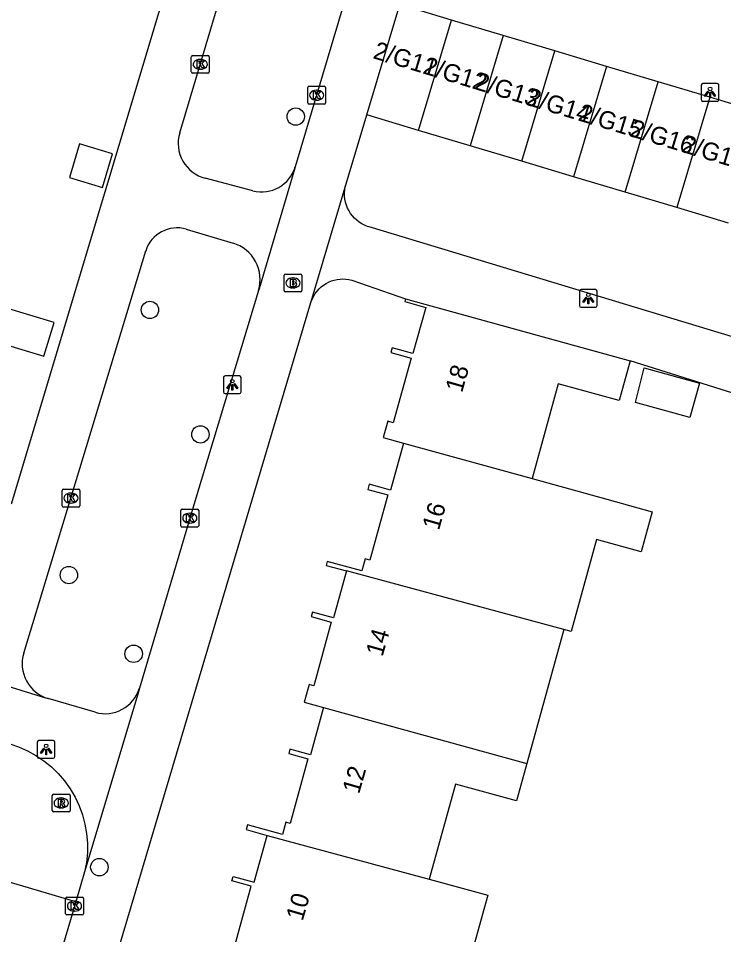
# Model space of a CAD drawing. Extents: x 162186 to 163152, y 385513 to 386513.
# Drawn here: x 162732.3 to 162772, y 386113.9 to 386165.5 of the extents above; entities that cross this region are included whole.
import ezdxf

# ---------------------------------------------------------------- set-up
doc = ezdxf.new("R2010")
doc.units = 0
for name, color, linetype in [('IMGEO_Boom', 7, 'Continuous'), ('IMGEO_Brandkraan', 7, 'Continuous'), ('IMGEO_Kolk', 7, 'Continuous'), ('IMGEO_Lichtpunt', 7, 'Continuous'), ('IMGEO_Pand', 7, 'Continuous'), ('IMGEO_Pand_nummerreeks', 7, 'Continuous'), ('IMGEO_Rijbaan_lokaal_open', 7, 'Continuous'), ('IMGEO_Rioolput', 7, 'Continuous'), ('IMGEO_Voetpad_open', 7, 'Continuous')]:
    doc.layers.add(name, color=color, linetype=linetype)

msp = doc.modelspace()

# ---------------------------------------------------------------- linework, layer by layer
at = {"layer": 'IMGEO_Boom'}
for centre in [(162747.869, 386159.924), (162739.661, 386149.049), (162742.506, 386142.04), (162735.099, 386134.127), (162738.747, 386129.698), (162736.815, 386117.693)]:
    msp.add_circle(centre, 0.489, dxfattribs=at)
at = {"layer": 'IMGEO_Brandkraan'}
for p, q in [((162747.21, 386150.141), (162747.21, 386150.993)), ((162747.285, 386151.067), (162748.137, 386151.067)), ((162748.211, 386150.993), (162748.211, 386150.141)), ((162747.698, 386150.847), (162747.723, 386150.847)), ((162748.137, 386150.067), (162747.285, 386150.067)), ((162747.721, 386150.287), (162747.696, 386150.287))]:
    msp.add_line(p, q, dxfattribs=at)
for points in [[(162747.21, 386150.141), (162747.21, 386150.993)], [(162747.285, 386151.067), (162748.137, 386151.067)], [(162748.211, 386150.993), (162748.211, 386150.141)], [(162747.558, 386150.767), (162747.558, 386150.367), (162747.771, 386150.367)], [(162747.789, 386150.767), (162747.558, 386150.767)], [(162747.737, 386150.686), (162747.683, 386150.686), (162747.683, 386150.61)], [(162747.683, 386150.61), (162747.736, 386150.61)], [(162747.745, 386150.534), (162747.683, 386150.534), (162747.683, 386150.453)], [(162747.683, 386150.453), (162747.745, 386150.453)], [(162748.137, 386150.067), (162747.285, 386150.067)]]:
    msp.add_lwpolyline(points, dxfattribs=at)
for centre, radius, start, end in [((162747.287, 386150.991), 0.0765, 91.552, 178.448), ((162747.287, 386150.991), 0.0765, 91.552, 178.448), ((162748.135, 386150.991), 0.0765, 1.552, 88.448), ((162748.135, 386150.991), 0.0765, 1.552, 88.448), ((162747.738, 386150.648), 0.0379, 267.8285, 90.9355), ((162747.746, 386150.493), 0.0404, 269.8759, 90.5077), ((162747.793, 386150.622), 0.145, 59.4692, 91.5367), ((162747.818, 386150.669), 0.0922, 285.5137, 58.1501), ((162747.823, 386150.477), 0.105, 301.3115, 78.989), ((162747.287, 386150.143), 0.0765, 181.552, 268.448), ((162747.287, 386150.143), 0.0765, 181.552, 268.448), ((162747.777, 386150.618), 0.251, 268.6676, 293.5347), ((162748.135, 386150.143), 0.0765, 271.552, 358.448), ((162748.135, 386150.143), 0.0765, 271.552, 358.448)]:
    msp.add_arc(centre, radius, start, end, dxfattribs=at)
for centre, major_axis, ratio, start_param, end_param in [((162747.697, 386150.567), (-0.387, 0.002), 0.722429, 4.712389, 7.853982), ((162747.722, 386150.567), (-0.39, 0.002), 0.717154, 1.570796, 4.712389)]:
    msp.add_ellipse(centre, major_axis=major_axis, ratio=ratio, start_param=start_param, end_param=end_param, dxfattribs=at)
at = {"layer": 'IMGEO_Kolk'}
for p, q in [((162742.068, 386163.365), (162742.92, 386163.365)), ((162741.993, 386162.439), (162741.993, 386163.291)), ((162742.481, 386163.145), (162742.506, 386163.145)), ((162742.994, 386163.291), (162742.994, 386162.439)), ((162742.92, 386162.365), (162742.068, 386162.365)), ((162742.504, 386162.585), (162742.479, 386162.585)), ((162748.544, 386160.702), (162748.544, 386161.554)), ((162748.619, 386161.628), (162749.471, 386161.628)), ((162749.032, 386161.408), (162749.057, 386161.408)), ((162749.545, 386161.554), (162749.545, 386160.702)), ((162749.055, 386160.848), (162749.03, 386160.848)), ((162749.471, 386160.628), (162748.619, 386160.628)), ((162734.718, 386138.031), (162734.718, 386138.883)), ((162734.793, 386138.957), (162735.645, 386138.957)), ((162735.206, 386138.737), (162735.231, 386138.737)), ((162735.719, 386138.883), (162735.719, 386138.031)), ((162735.229, 386138.177), (162735.204, 386138.177)), ((162735.645, 386137.957), (162734.793, 386137.957)), ((162741.407, 386136.905), (162741.407, 386137.757)), ((162741.482, 386137.831), (162742.334, 386137.831)), ((162741.895, 386137.611), (162741.92, 386137.611)), ((162742.408, 386137.757), (162742.408, 386136.905)), ((162741.918, 386137.051), (162741.893, 386137.051)), ((162742.334, 386136.831), (162741.482, 386136.831)), ((162734.917, 386115.077), (162734.917, 386115.929)), ((162734.992, 386116.003), (162735.844, 386116.003)), ((162735.918, 386115.929), (162735.918, 386115.077)), ((162735.405, 386115.783), (162735.43, 386115.783)), ((162735.844, 386115.003), (162734.992, 386115.003)), ((162735.428, 386115.223), (162735.403, 386115.223))]:
    msp.add_line(p, q, dxfattribs=at)
for points in [[(162742.068, 386163.365), (162742.92, 386163.365)], [(162741.993, 386162.439), (162741.993, 386163.291)], [(162742.314, 386163.065), (162742.437, 386163.065), (162742.437, 386162.914), (162742.567, 386163.065), (162742.731, 386163.065), (162742.585, 386162.914), (162742.738, 386162.665), (162742.586, 386162.665), (162742.501, 386162.829), (162742.437, 386162.762), (162742.437, 386162.665), (162742.314, 386162.665), (162742.314, 386163.065)], [(162742.994, 386163.291), (162742.994, 386162.439)], [(162742.92, 386162.365), (162742.068, 386162.365)], [(162748.544, 386160.702), (162748.544, 386161.554)], [(162748.619, 386161.628), (162749.471, 386161.628)], [(162748.865, 386161.328), (162748.988, 386161.328), (162748.988, 386161.177), (162749.118, 386161.328), (162749.282, 386161.328), (162749.136, 386161.177), (162749.289, 386160.928), (162749.137, 386160.928), (162749.052, 386161.092), (162748.988, 386161.025), (162748.988, 386160.928), (162748.865, 386160.928), (162748.865, 386161.328)], [(162749.545, 386161.554), (162749.545, 386160.702)], [(162749.471, 386160.628), (162748.619, 386160.628)], [(162734.718, 386138.031), (162734.718, 386138.883)], [(162734.793, 386138.957), (162735.645, 386138.957)], [(162735.039, 386138.657), (162735.162, 386138.657), (162735.162, 386138.506), (162735.292, 386138.657), (162735.456, 386138.657), (162735.31, 386138.506), (162735.463, 386138.257), (162735.311, 386138.257), (162735.226, 386138.421), (162735.162, 386138.354), (162735.162, 386138.257), (162735.039, 386138.257), (162735.039, 386138.657)], [(162735.719, 386138.883), (162735.719, 386138.031)], [(162735.645, 386137.957), (162734.793, 386137.957)], [(162741.407, 386136.905), (162741.407, 386137.757)], [(162741.482, 386137.831), (162742.334, 386137.831)], [(162742.408, 386137.757), (162742.408, 386136.905)], [(162741.728, 386137.531), (162741.851, 386137.531), (162741.851, 386137.38), (162741.981, 386137.531), (162742.145, 386137.531), (162741.999, 386137.38), (162742.152, 386137.131), (162742, 386137.131), (162741.915, 386137.295), (162741.851, 386137.228), (162741.851, 386137.131), (162741.728, 386137.131), (162741.728, 386137.531)], [(162742.334, 386136.831), (162741.482, 386136.831)], [(162734.917, 386115.077), (162734.917, 386115.929)], [(162734.992, 386116.003), (162735.844, 386116.003)], [(162735.918, 386115.929), (162735.918, 386115.077)], [(162735.238, 386115.703), (162735.361, 386115.703), (162735.361, 386115.552), (162735.491, 386115.703), (162735.655, 386115.703), (162735.509, 386115.552), (162735.662, 386115.303), (162735.51, 386115.303), (162735.425, 386115.467), (162735.361, 386115.4), (162735.361, 386115.303), (162735.238, 386115.303), (162735.238, 386115.703)], [(162735.844, 386115.003), (162734.992, 386115.003)]]:
    msp.add_lwpolyline(points, dxfattribs=at)
for centre, start, end in [((162742.07, 386163.289), 91.552, 178.448), ((162742.07, 386163.289), 91.552, 178.448), ((162742.918, 386163.289), 1.552, 88.448), ((162742.918, 386163.289), 1.552, 88.448), ((162742.07, 386162.441), 181.552, 268.448), ((162742.07, 386162.441), 181.552, 268.448), ((162742.918, 386162.441), 271.552, 358.448), ((162742.918, 386162.441), 271.552, 358.448), ((162748.621, 386161.552), 91.552, 178.448), ((162748.621, 386161.552), 91.552, 178.448), ((162749.469, 386161.552), 1.552, 88.448), ((162749.469, 386161.552), 1.552, 88.448), ((162748.621, 386160.704), 181.552, 268.448), ((162748.621, 386160.704), 181.552, 268.448), ((162749.469, 386160.704), 271.552, 358.448), ((162749.469, 386160.704), 271.552, 358.448), ((162734.795, 386138.881), 91.552, 178.448), ((162734.795, 386138.881), 91.552, 178.448), ((162735.643, 386138.881), 1.552, 88.448), ((162735.643, 386138.881), 1.552, 88.448), ((162734.795, 386138.033), 181.552, 268.448), ((162734.795, 386138.033), 181.552, 268.448), ((162735.643, 386138.033), 271.552, 358.448), ((162735.643, 386138.033), 271.552, 358.448), ((162741.484, 386137.755), 91.552, 178.448), ((162741.484, 386137.755), 91.552, 178.448), ((162742.332, 386137.755), 1.552, 88.448), ((162742.332, 386137.755), 1.552, 88.448), ((162741.484, 386136.907), 181.552, 268.448), ((162741.484, 386136.907), 181.552, 268.448), ((162742.332, 386136.907), 271.552, 358.448), ((162742.332, 386136.907), 271.552, 358.448), ((162734.994, 386115.927), 91.552, 178.448), ((162734.994, 386115.927), 91.552, 178.448), ((162735.842, 386115.927), 1.552, 88.448), ((162735.842, 386115.927), 1.552, 88.448), ((162734.994, 386115.079), 181.552, 268.448), ((162734.994, 386115.079), 181.552, 268.448), ((162735.842, 386115.079), 271.552, 358.448), ((162735.842, 386115.079), 271.552, 358.448)]:
    msp.add_arc(centre, 0.0765, start, end, dxfattribs=at)
for centre, major_axis, ratio, start_param, end_param in [((162742.48, 386162.865), (-0.387, 0.002), 0.722429, 4.712389, 7.853982), ((162742.505, 386162.865), (-0.39, 0.002), 0.717154, 1.570796, 4.712389), ((162749.031, 386161.128), (-0.387, 0.002), 0.722429, 4.712389, 7.853982), ((162749.056, 386161.128), (-0.39, 0.002), 0.717154, 1.570796, 4.712389), ((162735.205, 386138.457), (-0.387, 0.002), 0.722429, 4.712389, 7.853982), ((162735.23, 386138.457), (-0.39, 0.002), 0.717154, 1.570796, 4.712389), ((162741.894, 386137.331), (-0.387, 0.002), 0.722429, 4.712389, 7.853982), ((162741.919, 386137.331), (-0.39, 0.002), 0.717154, 1.570796, 4.712389), ((162735.404, 386115.503), (-0.387, 0.002), 0.722429, 4.712389, 7.853982), ((162735.429, 386115.503), (-0.39, 0.002), 0.717154, 1.570796, 4.712389)]:
    msp.add_ellipse(centre, major_axis=major_axis, ratio=ratio, start_param=start_param, end_param=end_param, dxfattribs=at)
at = {"layer": 'IMGEO_Lichtpunt'}
for p, q in [((162770.694, 386161.684), (162770.694, 386160.877)), ((162770.694, 386161.684), (162770.694, 386160.877)), ((162771.596, 386161.779), (162770.788, 386161.779)), ((162771.596, 386161.779), (162770.788, 386161.779)), ((162771.69, 386160.877), (162771.69, 386161.684)), ((162771.69, 386160.877), (162771.69, 386161.684)), ((162770.788, 386160.783), (162771.596, 386160.783)), ((162770.788, 386160.783), (162771.596, 386160.783)), ((162763.837, 386150.097), (162763.837, 386149.29)), ((162763.837, 386150.097), (162763.837, 386149.29)), ((162764.739, 386150.192), (162763.931, 386150.192)), ((162764.739, 386150.192), (162763.931, 386150.192)), ((162764.833, 386149.29), (162764.833, 386150.097)), ((162764.833, 386149.29), (162764.833, 386150.097)), ((162763.931, 386149.196), (162764.739, 386149.196)), ((162763.931, 386149.196), (162764.739, 386149.196)), ((162744.701, 386145.333), (162743.893, 386145.333)), ((162744.701, 386145.333), (162743.893, 386145.333)), ((162743.799, 386145.238), (162743.799, 386144.431)), ((162743.799, 386145.238), (162743.799, 386144.431)), ((162744.795, 386144.431), (162744.795, 386145.238)), ((162744.795, 386144.431), (162744.795, 386145.238)), ((162743.893, 386144.337), (162744.701, 386144.337)), ((162743.893, 386144.337), (162744.701, 386144.337)), ((162733.321, 386124.724), (162733.321, 386123.917)), ((162733.321, 386124.724), (162733.321, 386123.917)), ((162734.223, 386124.819), (162733.415, 386124.819)), ((162734.223, 386124.819), (162733.415, 386124.819)), ((162734.317, 386123.917), (162734.317, 386124.724)), ((162734.317, 386123.917), (162734.317, 386124.724)), ((162733.415, 386123.823), (162734.223, 386123.823)), ((162733.415, 386123.823), (162734.223, 386123.823))]:
    msp.add_line(p, q, dxfattribs=at)
for points in [[(162771.068, 386161.348), (162771.107, 386161.32), (162770.919, 386161.058), (162770.881, 386161.085), (162771.068, 386161.348)], [(162771.17, 386161.3), (162771.217, 386161.3), (162771.217, 386160.978), (162771.17, 386160.978), (162771.17, 386161.3)], [(162771.28, 386161.32), (162771.318, 386161.347), (162771.505, 386161.085), (162771.466, 386161.057), (162771.28, 386161.32)], [(162764.211, 386149.761), (162764.25, 386149.733), (162764.062, 386149.471), (162764.024, 386149.498), (162764.211, 386149.761)], [(162764.313, 386149.713), (162764.36, 386149.713), (162764.36, 386149.391), (162764.313, 386149.391), (162764.313, 386149.713)], [(162764.423, 386149.733), (162764.461, 386149.76), (162764.648, 386149.498), (162764.609, 386149.47), (162764.423, 386149.733)], [(162744.173, 386144.902), (162744.212, 386144.874), (162744.024, 386144.612), (162743.986, 386144.639), (162744.173, 386144.902)], [(162744.275, 386144.854), (162744.322, 386144.854), (162744.322, 386144.532), (162744.275, 386144.532), (162744.275, 386144.854)], [(162744.385, 386144.874), (162744.423, 386144.901), (162744.61, 386144.639), (162744.571, 386144.611), (162744.385, 386144.874)], [(162733.695, 386124.388), (162733.734, 386124.36), (162733.546, 386124.098), (162733.508, 386124.125), (162733.695, 386124.388)], [(162733.797, 386124.34), (162733.844, 386124.34), (162733.844, 386124.018), (162733.797, 386124.018), (162733.797, 386124.34)], [(162733.907, 386124.36), (162733.945, 386124.387), (162734.132, 386124.125), (162734.093, 386124.097), (162733.907, 386124.36)]]:
    msp.add_lwpolyline(points, dxfattribs=at)
for centre in [(162771.193, 386161.482), (162764.336, 386149.895), (162744.298, 386145.036), (162733.82, 386124.522)]:
    msp.add_circle(centre, 0.0994, dxfattribs=at)
for centre, start, end in [((162770.788, 386161.684), 90, 180), ((162770.788, 386161.684), 90, 180), ((162771.596, 386161.684), 0, 90), ((162771.596, 386161.684), 0, 90), ((162770.788, 386160.877), 180, 270), ((162770.788, 386160.877), 180, 270), ((162771.596, 386160.877), 270, 0), ((162771.596, 386160.877), 270, 360), ((162763.931, 386150.097), 90, 180), ((162763.931, 386150.097), 90, 180), ((162764.739, 386150.097), 0, 90), ((162764.739, 386150.097), 0, 90), ((162763.931, 386149.29), 180, 270), ((162763.931, 386149.29), 180, 270), ((162764.739, 386149.29), 270, 0), ((162764.739, 386149.29), 270, 360), ((162743.893, 386145.238), 90, 180), ((162743.893, 386145.238), 90, 180), ((162744.701, 386145.238), 0, 90), ((162744.701, 386145.238), 0, 90), ((162743.893, 386144.431), 180, 270), ((162743.893, 386144.431), 180, 270), ((162744.701, 386144.431), 270, 0), ((162744.701, 386144.431), 270, 360), ((162733.415, 386124.724), 90, 180), ((162733.415, 386124.724), 90, 180), ((162734.223, 386124.724), 0, 90), ((162734.223, 386124.724), 0, 90), ((162733.415, 386123.917), 180, 270), ((162733.415, 386123.917), 180, 270), ((162734.223, 386123.917), 270, 0), ((162734.223, 386123.917), 270, 360)]:
    msp.add_arc(centre, 0.0946, start, end, dxfattribs=at)
at = {"layer": 'IMGEO_Pand'}
for points in [[(162751.879, 386160.019), (162753.736, 386166.228)], [(162756.643, 386165.358), (162753.736, 386166.228)], [(162754.785, 386159.15), (162756.643, 386165.358)], [(162759.549, 386164.489), (162756.643, 386165.358)], [(162759.549, 386164.489), (162757.691, 386158.28)], [(162762.456, 386163.619), (162759.549, 386164.489)], [(162760.598, 386157.41), (162762.456, 386163.619)], [(162765.362, 386162.749), (162762.456, 386163.619)], [(162765.362, 386162.749), (162763.505, 386156.541)], [(162768.269, 386161.879), (162765.362, 386162.749)], [(162766.411, 386155.671), (162768.269, 386161.879)], [(162771.176, 386161.01), (162768.269, 386161.879)], [(162771.176, 386161.01), (162769.318, 386154.802)], [(162774.082, 386160.14), (162771.176, 386161.01)], [(162754.785, 386159.15), (162751.879, 386160.019)], [(162757.691, 386158.28), (162754.785, 386159.15)], [(162735.131, 386156.502), (162736.996, 386155.941), (162737.562, 386157.824), (162735.697, 386158.385), (162735.131, 386156.502)], [(162760.598, 386157.41), (162757.691, 386158.28)], [(162763.505, 386156.541), (162760.598, 386157.41)], [(162766.411, 386155.671), (162763.505, 386156.541)], [(162769.318, 386154.802), (162766.411, 386155.671)], [(162772.225, 386153.932), (162769.318, 386154.802)], [(162733.694, 386146.438), (162734.266, 386148.34), (162730.148, 386149.579), (162729.576, 386147.678), (162733.694, 386146.438)], [(162754.057, 386149.665), (162754.015, 386149.513), (162755.188, 386149.19), (162754.47, 386146.589), (162753.294, 386146.913), (162753.221, 386146.65), (162754.363, 386146.335), (162753.36, 386142.7), (162753.046, 386142.787), (162752.794, 386141.873), (162753.935, 386141.558)], [(162754.057, 386149.665), (162766.688, 386146.18)], [(162766.688, 386146.18), (162766.072, 386143.946), (162762.649, 386144.89), (162761.178, 386139.561)], [(162766.988, 386143.845), (162767.486, 386145.782), (162770.592, 386144.925), (162770.061, 386142.997), (162766.988, 386143.845)], [(162753.935, 386141.558), (162753.91, 386141.467), (162753.206, 386138.913), (162752.009, 386139.243), (162751.928, 386138.95), (162753.057, 386138.639), (162752.044, 386134.969), (162751.786, 386135.04), (162751.598, 386134.358), (162749.641, 386134.898), (162749.58, 386134.674), (162750.728, 386134.364)], [(162753.935, 386141.558), (162761.178, 386139.561)], [(162761.178, 386139.561), (162765.373, 386138.404), (162767.928, 386137.695), (162767.305, 386135.44), (162764.799, 386136.132), (162763.37, 386130.955), (162762.952, 386131.07)], [(162750.728, 386134.364), (162749.997, 386131.716), (162748.806, 386132.045), (162748.735, 386131.788), (162749.868, 386131.475), (162748.88, 386127.895), (162748.618, 386127.967), (162748.344, 386126.976), (162749.428, 386126.677)], [(162762.952, 386131.07), (162750.728, 386134.364)], [(162762.952, 386131.07), (162760.871, 386123.521)], [(162749.428, 386126.677), (162749.414, 386126.625), (162748.694, 386124.017), (162747.542, 386124.334), (162747.473, 386124.083), (162748.558, 386123.783), (162747.556, 386120.152), (162747.307, 386120.221), (162747.118, 386119.533), (162745.155, 386120.075), (162745.081, 386119.807), (162746.257, 386119.483)], [(162749.428, 386126.677), (162760.871, 386123.521)], [(162760.871, 386123.521), (162760.292, 386121.421), (162756.863, 386122.367), (162755.389, 386117.025)], [(162744.982, 386111.839), (162743.872, 386112.145), (162744.129, 386113.077), (162744.368, 386113.011), (162745.366, 386116.628), (162744.272, 386116.931), (162744.34, 386117.177), (162745.53, 386116.849), (162746.257, 386119.483)], [(162746.257, 386119.483), (162755.389, 386117.025)], [(162755.389, 386117.025), (162757.653, 386116.399), (162758.675, 386116.117), (162756.608, 386108.631)]]:
    msp.add_lwpolyline(points, dxfattribs=at)
at = {"layer": 'IMGEO_Rijbaan_lokaal_open'}
for points in [[(162701.942, 386133.579), (162731.827, 386124.614), (162732.274, 386124.461), (162732.77, 386124.243), (162733.245, 386123.981), (162733.695, 386123.678), (162734.116, 386123.336), (162734.504, 386122.958), (162734.857, 386122.547), (162735.172, 386122.105), (162735.447, 386121.638), (162735.678, 386121.148), (162735.865, 386120.639), (162736.005, 386120.115), (162736.099, 386119.581), (162736.144, 386119.041), (162736.14, 386118.499), (162736.089, 386117.959), (162735.989, 386117.426)], [(162735.486, 386115.734), (162730.846, 386117.114)], [(162735.989, 386117.426), (162735.486, 386115.734)], [(162735.486, 386115.734), (162730.41, 386098.664), (162727.044, 386087.256)]]:
    msp.add_lwpolyline(points, dxfattribs=at)
at = {"layer": 'IMGEO_Rioolput'}
for p, q in [((162734.168, 386120.88), (162734.168, 386121.732)), ((162734.243, 386121.806), (162735.095, 386121.806)), ((162734.656, 386121.586), (162734.681, 386121.586)), ((162735.169, 386121.732), (162735.169, 386120.88)), ((162735.095, 386120.806), (162734.243, 386120.806)), ((162734.679, 386121.026), (162734.654, 386121.026))]:
    msp.add_line(p, q, dxfattribs=at)
for points in [[(162734.168, 386120.88), (162734.168, 386121.732)], [(162734.243, 386121.806), (162735.095, 386121.806)], [(162735.169, 386121.732), (162735.169, 386120.88)], [(162734.757, 386121.504), (162734.505, 386121.506), (162734.505, 386121.106)], [(162734.505, 386121.106), (162734.629, 386121.106), (162734.629, 386121.268), (162734.64, 386121.268)], [(162734.683, 386121.425), (162734.629, 386121.425), (162734.629, 386121.344)], [(162734.629, 386121.344), (162734.681, 386121.344)], [(162734.687, 386121.239), (162734.758, 386121.106), (162734.898, 386121.106), (162734.833, 386121.232)], [(162735.095, 386120.806), (162734.243, 386120.806)]]:
    msp.add_lwpolyline(points, dxfattribs=at)
for centre, radius, start, end in [((162734.245, 386121.73), 0.0765, 91.552, 178.448), ((162734.245, 386121.73), 0.0765, 91.552, 178.448), ((162735.093, 386121.73), 0.0765, 1.552, 88.448), ((162735.093, 386121.73), 0.0765, 1.552, 88.448), ((162734.639, 386121.215), 0.0533, 26.0293, 88.6989), ((162734.665, 386121.533), 0.19, 274.7715, 282.9687), ((162734.689, 386121.329), 0.0964, 77.0061, 93.1865), ((162734.703, 386121.386), 0.0378, 276.6634, 79.6772), ((162734.756, 386121.394), 0.109, 350.3612, 89.416), ((162734.754, 386121.394), 0.112, 277.5842, 350.9817), ((162734.738, 386121.179), 0.108, 29.5134, 73.7905), ((162734.245, 386120.882), 0.0765, 181.552, 268.448), ((162734.245, 386120.882), 0.0765, 181.552, 268.448), ((162735.093, 386120.882), 0.0765, 271.552, 358.448), ((162735.093, 386120.882), 0.0765, 271.552, 358.448)]:
    msp.add_arc(centre, radius, start, end, dxfattribs=at)
for centre, major_axis, ratio, start_param, end_param in [((162734.655, 386121.306), (-0.387, 0.002), 0.722429, 4.712389, 7.853982), ((162734.68, 386121.306), (-0.39, 0.002), 0.717154, 1.570796, 4.712389)]:
    msp.add_ellipse(centre, major_axis=major_axis, ratio=ratio, start_param=start_param, end_param=end_param, dxfattribs=at)
at = {"layer": 'IMGEO_Voetpad_open'}
for points in [[(162745.642, 386194.214), (162745.895, 386194.111), (162746.139, 386193.986), (162746.37, 386193.84), (162746.588, 386193.673), (162746.789, 386193.488), (162746.974, 386193.285), (162747.139, 386193.067), (162747.284, 386192.835), (162747.408, 386192.59), (162747.51, 386192.336), (162747.588, 386192.074), (162747.643, 386191.805), (162747.674, 386191.533), (162747.68, 386191.259), (162747.661, 386190.986), (162747.619, 386190.716), (162747.552, 386190.45), (162731.855, 386138.123)], [(162741.339, 386159.002), (162750.76, 386190.615)], [(162757.217, 386188.564), (162747.844, 386157.099)], [(162750.699, 386156.134), (162751.879, 386160.019)], [(162747.844, 386157.099), (162747.828, 386157.024), (162745.815, 386150.242), (162745.775, 386150.139)], [(162745.456, 386155.754), (162742.772, 386156.454)], [(162748.746, 386149.525), (162750.699, 386156.134)], [(162779.405, 386145.432), (162751.997, 386153.715), (162751.909, 386153.744), (162751.748, 386153.809), (162751.594, 386153.889), (162751.447, 386153.982), (162751.309, 386154.088), (162751.181, 386154.206), (162751.064, 386154.334), (162750.96, 386154.473), (162750.868, 386154.621), (162750.789, 386154.776), (162750.725, 386154.937), (162750.675, 386155.104), (162750.64, 386155.274), (162750.621, 386155.447), (162750.617, 386155.62), (162750.629, 386155.794), (162750.657, 386155.965), (162750.699, 386156.134)], [(162741.707, 386153.587), (162744.341, 386152.804)], [(162732.559, 386129.74), (162739.429, 386152.362)], [(162748.746, 386149.525), (162748.807, 386149.68), (162748.881, 386149.829), (162748.969, 386149.971), (162749.068, 386150.105), (162749.18, 386150.229), (162749.302, 386150.342), (162749.433, 386150.445), (162749.574, 386150.535), (162749.721, 386150.612), (162749.875, 386150.676), (162750.034, 386150.726), (162750.197, 386150.761), (162750.363, 386150.782), (162750.529, 386150.788), (162750.696, 386150.779), (162750.861, 386150.755), (162751.023, 386150.716), (162754.057, 386149.665)], [(162745.775, 386150.139), (162742.241, 386138.459), (162739.071, 386127.769)], [(162729.962, 386086.464), (162748.726, 386149.462), (162748.746, 386149.525)], [(162780.193, 386139.71), (162780.226, 386139.918), (162780.241, 386140.129), (162780.237, 386140.34), (162780.214, 386140.55), (162780.172, 386140.757), (162780.112, 386140.959), (162780.034, 386141.155), (162779.939, 386141.344), (162779.828, 386141.523), (162779.7, 386141.692), (162779.559, 386141.848), (162779.404, 386141.992), (162779.236, 386142.121), (162779.058, 386142.234), (162778.871, 386142.331), (162778.675, 386142.411), (162778.556, 386142.45), (162766.688, 386146.18)], [(162733.94, 386127.181), (162733.805, 386127.21), (162727.389, 386129.185)], [(162739.071, 386127.769), (162739.041, 386127.618), (162735.989, 386117.426)], [(162736.572, 386126.411), (162733.94, 386127.181)]]:
    msp.add_lwpolyline(points, dxfattribs=at)
for centre, radius, start, end in [((162743.284, 386158.419), 2.031, 163.3163, 255.3907), ((162745.954, 386157.662), 1.972, 255.3735, 343.4058), ((162741.183, 386151.831), 1.832, 73.3805, 163.158), ((162743.729, 386150.756), 2.137, 343.2082, 73.36), ((162734.514, 386129.143), 2.044, 163.0079, 253.7003), ((162737.137, 386128.349), 2.019, 253.7328, 343.3081)]:
    msp.add_arc(centre, radius, start, end, dxfattribs=at)

# ---------------------------------------------------------------- texts
at = {"layer": 'IMGEO_Pand_nummerreeks'}
for s, rotation, p in [('2/G11', 343.1416, (162752.172, 386163.217)), ('2/G12', 343.1416, (162754.97, 386162.369)), ('2/G13', 343.1416, (162757.887, 386161.485)), ('2/G14', 343.1416, (162760.797, 386160.603)), ('2/G15', 343.1416, (162763.708, 386159.722)), ('2/G16', 343.1416, (162766.618, 386158.84)), ('2/G17', 343.1416, (162769.529, 386157.958)), ('18', 74.2668, (162757.231, 386144.351)), ('16', 73.9803, (162755.927, 386136.606)), ('14', 74.0491, (162752.751, 386129.5)), ('12', 73.986, (162751.434, 386121.773)), ('10', 73.7282, (162748.256, 386114.625))]:
    msp.add_text(s, height=1, rotation=rotation, dxfattribs=at).set_placement(p)

doc.saveas('drawing.dxf')
